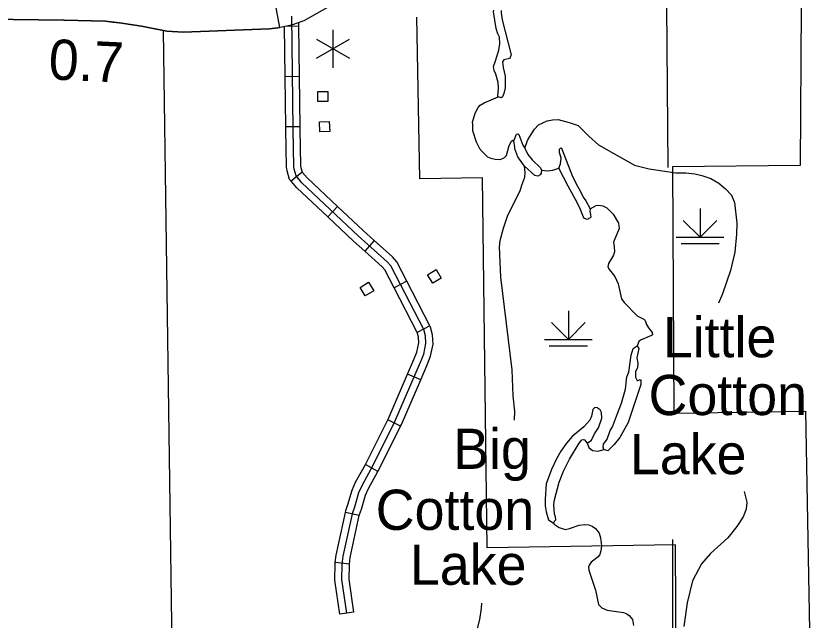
# Model space of a CAD drawing. Extents: x 1084508 to 1142749, y 1057638 to 1093403.
# Drawn here: x 1098889 to 1101507, y 1085702 to 1087695 of the extents above; entities that cross this region are included whole.
import ezdxf

# ---------------------------------------------------------------- set-up
doc = ezdxf.new("R2010")
doc.units = 0
for name, color, linetype in [('Level 10', 7, 'Continuous'), ('Level 32', 7, 'Continuous'), ('Level 35', 7, 'Continuous'), ('Level 44', 7, 'Continuous'), ('Level 47', 7, 'Continuous'), ('Level 48', 7, 'Continuous'), ('Level 5', 7, 'Continuous'), ('Level 56', 7, 'Continuous'), ('Level 7', 7, 'Continuous')]:
    doc.layers.add(name, color=color, linetype=linetype)

msp = doc.modelspace()

# ---------------------------------------------------------------- linework, layer by layer
at = {"layer": 'Level 10'}
msp.add_line((1099759.1, 1087657.1), (1099744.3, 1087733.9), dxfattribs=at)
for points in [[(1100427.9, 1087848.4), (1100218.4, 1087864.7), (1100181.2, 1087861.9), (1100163.5, 1087858.1), (1100132.8, 1087846.5), (1099837.8, 1087678.9), (1099797, 1087664.4), (1099754.3, 1087656.2)], [(1099047.9, 1087681.2), (1098795, 1087683.9)], [(1098795.1, 1087683.9), (1099047.6, 1087681.2)], [(1099303, 1087661.1), (1099230.2, 1087672.6), (1099184, 1087677.3), (1099047.2, 1087681.2)], [(1099047.6, 1087681.2), (1099184, 1087677.3), (1099209.2, 1087674.8)], [(1099209.2, 1087674.8), (1099230.2, 1087672.6), (1099303, 1087661.1)], [(1099751.4, 1087655.7), (1099724.6, 1087652.6), (1099440, 1087641.1), (1099387.1, 1087645.1), (1099303, 1087661.1)], [(1099303, 1087661.1), (1099387.1, 1087645.1), (1099440, 1087641.1), (1099724.6, 1087652.6), (1099752.9, 1087655.9)], [(1099752.9, 1087655.9), (1099759.1, 1087657.1)]]:
    msp.add_lwpolyline(points, dxfattribs=at)
at = {"layer": 'Level 32'}
for p, q in [((1099822.1, 1087660.8), (1099775.5, 1087660.2)), ((1099824.2, 1087495.1), (1099777.1, 1087494.5)), ((1099826.3, 1087329.4), (1099779.2, 1087328.8)), ((1099832.4, 1087180.2), (1099796.4, 1087149.8)), ((1099949.1, 1087066.7), (1099916.9, 1087032.3)), ((1100070.3, 1086954.4), (1100038.8, 1086919.4)), ((1100177.6, 1086820.2), (1100135.8, 1086798.6)), ((1100253.6, 1086673), (1100211.8, 1086651.4)), ((1100223.6, 1086495), (1100180.4, 1086513.7)), ((1100157.1, 1086341.9), (1100114.9, 1086362.8)), ((1100082.4, 1086192.9), (1100041.1, 1086215.5)), ((1100021.1, 1086047.1), (1099975.1, 1086057)), ((1099988.7, 1085887), (1099942, 1085892.4)), ((1100003.1, 1085728.6), (1099956.5, 1085721.8))]:
    msp.add_line(p, q, dxfattribs=at)
for points in [[(1099802.8, 1087320.8), (1099798.1, 1087693.9)], [(1099777.1, 1087494.5), (1099775, 1087660.2)], [(1099822.1, 1087660.8), (1099821.9, 1087673.3)], [(1099824.2, 1087495.1), (1099822.1, 1087660.8)], [(1099779.2, 1087328.8), (1099777.1, 1087494.5)], [(1099826.3, 1087329.4), (1099824.2, 1087495.1)], [(1099796.4, 1087149.8), (1099791.3, 1087155.9), (1099783.1, 1087184.6), (1099781.5, 1087196.8), (1099779.3, 1087320.4), (1099779.2, 1087328.8)], [(1099979.8, 1085725.2), (1099963.7, 1085835.9), (1099965, 1085887), (1099968.1, 1085912.9), (1099999.4, 1086057.7), (1100006.1, 1086075.9), (1100019.5, 1086122.9), (1100030.1, 1086146.5), (1100068, 1086215.6), (1100138.4, 1086357.2), (1100222.9, 1086552.7), (1100233.2, 1086579.8), (1100240.3, 1086614.6), (1100239.3, 1086639.5), (1100233.6, 1086660.4), (1100125, 1086870.8), (1100113.3, 1086884), (1100017.7, 1086970.1), (1099831.7, 1087144.5), (1099812.5, 1087167.3), (1099806.2, 1087189.4), (1099805, 1087198.5), (1099802.8, 1087320.8)], [(1099833.8, 1087178.6), (1099829.3, 1087194.2), (1099828.5, 1087200.3), (1099826.4, 1087321.1), (1099826.3, 1087329.4)], [(1099949.1, 1087066.7), (1099848.8, 1087160.7), (1099832.4, 1087180.2)], [(1099916.9, 1087032.3), (1099814.6, 1087128.3), (1099796.4, 1087149.8)], [(1100070.3, 1086954.4), (1100033.6, 1086987.4), (1099949.1, 1087066.7)], [(1100038.8, 1086919.4), (1100001.7, 1086952.7), (1099916.9, 1087032.3)], [(1100177.6, 1086820.2), (1100144.5, 1086884.2), (1100130, 1086900.6), (1100070.3, 1086954.4)], [(1100135.8, 1086798.6), (1100105.4, 1086857.4), (1100096.5, 1086867.4), (1100038.8, 1086919.4)], [(1100253.6, 1086673), (1100177.6, 1086820.2)], [(1100211.8, 1086651.4), (1100135.8, 1086798.6)], [(1100223.6, 1086495), (1100244.8, 1086543.9), (1100255.8, 1086573.2), (1100264, 1086612.7), (1100262.7, 1086643.1), (1100255.7, 1086669), (1100253.6, 1086673)], [(1100180.4, 1086513.7), (1100201.1, 1086561.6), (1100210.5, 1086586.4), (1100216.7, 1086616.5), (1100215.9, 1086635.9), (1100211.6, 1086651.9), (1100211.8, 1086651.4)], [(1100114.9, 1086362.8), (1100117, 1086367.1), (1100180.4, 1086513.7)], [(1100157.1, 1086341.9), (1100159.8, 1086347.3), (1100223.6, 1086495)], [(1100041.1, 1086215.5), (1100047.1, 1086226.5), (1100114.9, 1086362.8)], [(1100082.4, 1086192.9), (1100088.9, 1086204.7), (1100157.1, 1086341.9)], [(1099975.1, 1086057), (1099976.7, 1086064.3), (1099983.7, 1086083.2), (1099997.3, 1086131), (1100009, 1086157), (1100041.1, 1086215.5)], [(1100021.1, 1086047.1), (1100022, 1086051.1), (1100028.4, 1086068.5), (1100041.6, 1086114.8), (1100051.2, 1086136), (1100082.4, 1086192.9)], [(1099942, 1085892.4), (1099944.8, 1085916.7), (1099975.1, 1086057)], [(1099988.7, 1085887), (1099991.3, 1085909), (1100021.1, 1086047.1)], [(1099956.5, 1085721.8), (1099940.1, 1085834.5), (1099941.5, 1085888.6), (1099942, 1085892.4)], [(1100003.1, 1085728.6), (1099987.3, 1085837.3), (1099988.5, 1085885.3), (1099988.7, 1085887)]]:
    msp.add_lwpolyline(points, dxfattribs=at)
at = {"layer": 'Level 35'}
for points in [[(1100482.9, 1087625.1), (1100478, 1087635.6), (1100471.9, 1087653.6), (1100463.7, 1087709.1), (1100464.1, 1087713.6)], [(1100488.9, 1087712.8), (1100488.1, 1087705.4), (1100491.5, 1087682.5), (1100521.5, 1087566.7), (1100518.7, 1087557.5), (1100515.7, 1087554.8)], [(1100394.6, 1087341.2), (1100394.5, 1087344.4), (1100403.3, 1087374), (1100412.7, 1087393), (1100419.9, 1087400.9), (1100432.2, 1087408.9), (1100478.3, 1087427.8), (1100477.3, 1087429.4), (1100480, 1087456.6), (1100478.6, 1087475.4), (1100471.5, 1087502.6), (1100465.3, 1087515.3), (1100463.5, 1087527.8), (1100469.7, 1087547.3), (1100480.5, 1087581.8), (1100484.1, 1087603.4), (1100482.9, 1087625.1)], [(1100515.7, 1087554.8), (1100497.6, 1087550.6), (1100493.5, 1087543.2), (1100495.2, 1087524.7), (1100501.4, 1087496.2), (1100501.4, 1087458.1), (1100497.7, 1087439), (1100493.1, 1087427.8), (1100488.3, 1087424.6)], [(1100488.3, 1087424.6), (1100478.3, 1087427.8)], [(1100394.6, 1087341.2), (1100393.7, 1087316.8), (1100405.8, 1087280.3), (1100417.4, 1087257.9), (1100425.6, 1087248.4), (1100443.7, 1087230.6), (1100454.8, 1087225.9), (1100468.8, 1087222.6), (1100484.5, 1087221.8), (1100490.8, 1087223.2), (1100499.4, 1087228.5), (1100505.8, 1087235), (1100515.2, 1087268), (1100522.4, 1087282.1), (1100527.3, 1087285), (1100530.8, 1087283.6)], [(1100530.8, 1087283.6), (1100539, 1087304.9), (1100543.1, 1087306.3), (1100546.6, 1087304.5), (1100560.2, 1087268.7), (1100566.8, 1087259.1), (1100576.2, 1087237.6), (1100591.2, 1087220.1), (1100618.7, 1087193.5), (1100621.4, 1087186.7), (1100620.4, 1087176.9), (1100616.8, 1087170.5), (1100609.1, 1087166.2), (1100599.3, 1087168.4), (1100565, 1087199.5), (1100544, 1087230.4), (1100533.5, 1087256.2), (1100534, 1087261.6), (1100530.8, 1087283.6)], [(1100678.4, 1087193.4), (1100683.7, 1087207.4), (1100686.6, 1087226.4), (1100680.7, 1087244.1), (1100681.3, 1087256.1), (1100685.6, 1087260), (1100687.5, 1087258.5), (1100724.2, 1087166), (1100740.2, 1087133.7), (1100749.5, 1087118.6), (1100759.2, 1087097.8), (1100768.1, 1087085.4), (1100781.4, 1087059), (1100780.4, 1087049.6), (1100783.5, 1087040.2), (1100783.8, 1087031.7), (1100782, 1087029.1), (1100772.4, 1087024.1), (1100763.8, 1087026.7), (1100759.9, 1087031.3), (1100749.4, 1087058.7), (1100740.6, 1087077.1), (1100709.1, 1087133.2), (1100678.4, 1087193.4)], [(1100621.4, 1087186.7), (1100641.3, 1087184.1), (1100658.5, 1087186.8), (1100678.4, 1087193.4)], [(1100781.4, 1087059), (1100802.2, 1087069.7), (1100810.6, 1087071.2), (1100824.2, 1087069.1), (1100837, 1087061.6), (1100857.7, 1087040.8), (1100875.3, 1087011.1), (1100878, 1086993.5), (1100858.5, 1086948.8), (1100861.5, 1086934.1), (1100862.3, 1086916.5), (1100858.5, 1086906.3), (1100842.1, 1086878.4), (1100840.5, 1086867.1), (1100845.5, 1086857.7), (1100862.8, 1086835.9), (1100874.5, 1086811.7), (1100884.8, 1086762.2), (1100893.6, 1086749.9), (1100936.4, 1086706.1), (1100959, 1086695.4), (1100963.6, 1086690.8), (1100968.1, 1086677.4), (1100973.7, 1086666.8), (1100986.1, 1086651.4), (1100987, 1086643.6), (1100983.6, 1086641), (1100948.2, 1086626.1), (1100942.3, 1086621.8), (1100936.8, 1086607.5)], [(1100827, 1086264.8), (1100824.5, 1086273.2), (1100826.1, 1086282.7), (1100838.2, 1086299.4), (1100848.4, 1086327.7), (1100855.6, 1086339.6), (1100871.6, 1086383.9), (1100885.1, 1086417.6), (1100897.9, 1086463.7), (1100903.3, 1086504.5), (1100909.1, 1086520.1), (1100917.6, 1086576.4), (1100924.2, 1086598), (1100936.8, 1086607.5), (1100942.7, 1086597.9), (1100935.7, 1086567.5), (1100939.4, 1086549.9), (1100937.9, 1086536), (1100931.7, 1086521.4), (1100931.6, 1086504), (1100936.4, 1086492.5), (1100940.1, 1086492.3), (1100946.6, 1086495.6), (1100949.2, 1086492.9), (1100948.4, 1086479), (1100906.7, 1086354.3), (1100879.9, 1086304.4), (1100860.5, 1086281.2), (1100840.3, 1086260.7), (1100827, 1086264.8)], [(1100772.6, 1086285.5), (1100786.1, 1086295.4), (1100796.2, 1086317.1), (1100809.5, 1086336.4), (1100820.2, 1086368.8), (1100819.3, 1086387.1), (1100815, 1086395.8), (1100805, 1086402.7), (1100797.8, 1086403.8), (1100790.4, 1086397.2), (1100786.6, 1086375.4), (1100781.1, 1086361.7), (1100760.6, 1086340.3), (1100722.6, 1086307.7), (1100704, 1086285.4), (1100685.3, 1086259.7), (1100671, 1086233.8), (1100654.1, 1086198.9), (1100636.9, 1086152.1), (1100633.3, 1086101.7), (1100634, 1086079.6), (1100636.4, 1086059.5), (1100645.1, 1086032.7), (1100660.4, 1086023.1), (1100668.3, 1086032.7), (1100667.7, 1086042.8), (1100664.3, 1086051.8), (1100662.4, 1086083.9), (1100664.2, 1086098.5), (1100679.8, 1086156.9), (1100694.1, 1086194.1), (1100713.4, 1086233.1), (1100746.2, 1086286), (1100754.6, 1086297.3), (1100760, 1086298.4), (1100763.8, 1086297.3), (1100772.6, 1086285.5)], [(1100772.6, 1086285.5), (1100772.7, 1086283.3), (1100777.4, 1086271.8), (1100789.6, 1086262.1), (1100808.3, 1086259.2), (1100827, 1086264.8)], [(1100660.4, 1086023.1), (1100663.1, 1086019.1), (1100679.8, 1086007.9), (1100699.1, 1086001.5), (1100713.5, 1086004.8), (1100746.2, 1086015.5), (1100764.1, 1086018.2), (1100777.6, 1086016.4), (1100788.1, 1086012), (1100799.4, 1086004.7), (1100811.4, 1085989), (1100816, 1085974), (1100819.3, 1085947.7), (1100817.2, 1085931.2), (1100813.8, 1085918.9), (1100808.7, 1085911.5), (1100785.3, 1085893.5), (1100778.4, 1085883.8), (1100776.4, 1085877.1), (1100777.6, 1085867.1), (1100799.6, 1085801.3), (1100809.8, 1085754), (1100820.2, 1085743.3), (1100838.4, 1085735.3), (1100891.4, 1085727.1), (1100903.2, 1085723), (1100910.9, 1085717.9), (1100921.7, 1085704.7), (1100924.8, 1085684.3)]]:
    msp.add_lwpolyline(points, dxfattribs=at)
at = {"layer": 'Level 44'}
for p, q in [((1101144.2, 1087059.5), (1101144.2, 1086965.4)), ((1101144.2, 1086965.4), (1101088.7, 1087020.8)), ((1101144.2, 1086965.4), (1101199.7, 1087020.8)), ((1101065.7, 1086965.4), (1101222.7, 1086965.4)), ((1101081.4, 1086944), (1101207, 1086944)), ((1100710, 1086722.5), (1100710, 1086628.3)), ((1100710, 1086628.3), (1100654.6, 1086683.8)), ((1100710, 1086628.3), (1100765.5, 1086683.8)), ((1100631.6, 1086628.3), (1100788.5, 1086628.3)), ((1100647.3, 1086606.9), (1100772.8, 1086606.9))]:
    msp.add_line(p, q, dxfattribs=at)
at = {"layer": 'Level 47'}
for points in [[(1100566.8, 1087259.1), (1100575.5, 1087283.9), (1100582.6, 1087297.4), (1100598.3, 1087321.8), (1100611.4, 1087335.4), (1100639.9, 1087349.1), (1100657.8, 1087352.1), (1100676.9, 1087353.3), (1100713, 1087344), (1100741.9, 1087333.8), (1100777, 1087298), (1100809.9, 1087269.6), (1100927.6, 1087202.5), (1100976, 1087190.7), (1101064.8, 1087177.2), (1101097.5, 1087177.5), (1101126.8, 1087174), (1101150.5, 1087169.3), (1101179.5, 1087159.1), (1101206, 1087143.2), (1101228.2, 1087125.3), (1101247.8, 1087103.5), (1101257.6, 1087079.2), (1101264.9, 1087011), (1101264.1, 1086975.4), (1101258.6, 1086916.1), (1101244, 1086855.2), (1101217.6, 1086778.8), (1101205.2, 1086747.8)], [(1100533, 1086361.4), (1100534, 1086391.4), (1100528.7, 1086441.6), (1100525.2, 1086528.1), (1100487.7, 1086833.5), (1100482.6, 1086933.8), (1100485.4, 1086954.1), (1100496.2, 1086995.3), (1100510.3, 1087037.6), (1100551.7, 1087117.9), (1100556.5, 1087136.9), (1100566.4, 1087163.7), (1100567.2, 1087178.8), (1100565, 1087199.5)], [(1101289, 1086126.8), (1101298.1, 1086091.7), (1101295.9, 1086068), (1101286, 1086042.5), (1101265.5, 1086011.4), (1101235.8, 1085973.6), (1101178.5, 1085922.5), (1101148.4, 1085887.6), (1101118.9, 1085832), (1101101.2, 1085759.7), (1101091.2, 1085681.3)], [(1100409.7, 1085670.3), (1100418.5, 1085704.5), (1100423.7, 1085742.2), (1100425, 1085758.5)]]:
    msp.add_lwpolyline(points, dxfattribs=at)
at = {"layer": 'Level 48'}
for p, q in [((1099934.5, 1087523.9), (1099934.5, 1087649.4)), ((1099880.1, 1087618), (1099988.9, 1087555.3)), ((1099880.1, 1087555.3), (1099988.9, 1087618))]:
    msp.add_line(p, q, dxfattribs=at)
at = {"layer": 'Level 5'}
for points in [[(1101039.2, 1087195.6), (1101034.4, 1087728.1)], [(1099374.3, 1087646), (1099403.9, 1085535.5), (1099408.8, 1083885.1)], [(1101051.2, 1083897.4), (1101054.7, 1085968.6)]]:
    msp.add_lwpolyline(points, dxfattribs=at)
at = {"layer": 'Level 56'}
for points in [[(1099884.2, 1087413), (1099884.2, 1087445.7), (1099917, 1087445.7), (1099917, 1087413)], [(1099890.6, 1087313), (1099889.3, 1087345.6), (1099922.1, 1087347), (1099923.4, 1087314.3)], [(1100291.3, 1086830.6), (1100263.6, 1086813.3), (1100246.2, 1086841.1), (1100273.9, 1086858.4)], [(1100068.4, 1086788.8), (1100040.8, 1086771.5), (1100023.4, 1086799.2), (1100051, 1086816.6)]]:
    msp.add_lwpolyline(points, close=True, dxfattribs=at)
at = {"layer": 'Level 7'}
msp.add_lwpolyline([(1101477.5, 1087724.7), (1101473.7, 1087201.9), (1101052.8, 1087197.5), (1101057.7, 1086384.8), (1101491.5, 1086391.5), (1101506.9, 1085546.8), (1101065.9, 1085540.6), (1101062.7, 1085951.1), (1100442.6, 1085940.8), (1100427.1, 1087160.8), (1100220.9, 1087158.2), (1100210.3, 1087690.5)], dxfattribs=at)

# ---------------------------------------------------------------- texts
at = {"layer": 'Level 35'}
for s, p in [('Little', (1101021.2, 1086569.2)), ('Cotton', (1100974.4, 1086378.5)), ('Big', (1100330.3, 1086201)), ('Lake', (1100912.8, 1086183.5)), ('Cotton', (1100075.1, 1085999.9)), ('Lake', (1100187.7, 1085818.8))]:
    msp.add_text(s, height=132.58, dxfattribs=at).set_placement(p)
at = {"layer": 'Level 48'}
msp.add_text('0.7', height=132.58, rotation=357.3163, dxfattribs=at).set_placement((1098994.9, 1087486.4))

doc.saveas('drawing.dxf')
